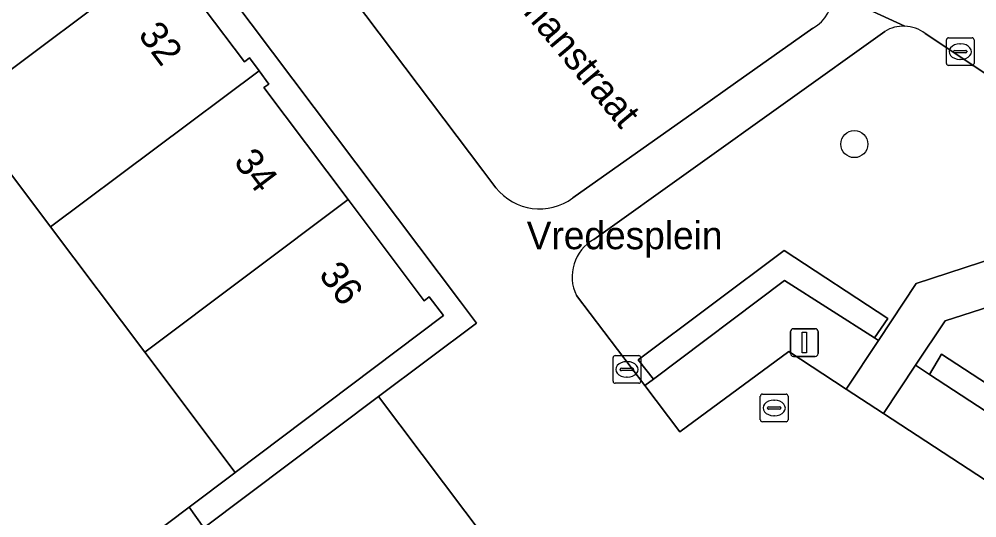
# Model space of a CAD drawing. Extents: x 160377 to 161131, y 383938 to 384853.
# Drawn here: x 160587.58 to 160622.12, y 384619.15 to 384637.16 of the extents above; entities that cross this region are included whole.
import ezdxf

# ---------------------------------------------------------------- set-up
doc = ezdxf.new("R2010")
doc.units = 0
for name, color, linetype in [('IMGEO_Boom', 7, 'Continuous'), ('IMGEO_Erf', 7, 'Continuous'), ('IMGEO_Groenvoorziening', 7, 'Continuous'), ('IMGEO_Kolk', 7, 'Continuous'), ('IMGEO_Lichtmast', 7, 'Continuous'), ('IMGEO_Muur', 7, 'Continuous'), ('IMGEO_Openbare_ruimte_label', 7, 'Continuous'), ('IMGEO_Pand', 7, 'Continuous'), ('IMGEO_Pand_nummerreeks', 7, 'Continuous'), ('IMGEO_Rioolput', 7, 'Continuous'), ('IMGEO_Voetgangersgebied_open', 7, 'Continuous')]:
    doc.layers.add(name, color=color, linetype=linetype)

msp = doc.modelspace()

# ---------------------------------------------------------------- linework, layer by layer
at = {"layer": 'IMGEO_Boom'}
msp.add_circle((160617.703, 384632.647), 0.489, dxfattribs=at)
at = {"layer": 'IMGEO_Erf'}
for points in [[(160586.32, 384648.095), (160589.204, 384644.259), (160589.374, 384644.4), (160589.733, 384643.922), (160590.092, 384643.444), (160589.923, 384643.302), (160592.795, 384639.483), (160595.702, 384635.617), (160595.883, 384635.76), (160596.236, 384635.288), (160596.588, 384634.816), (160596.403, 384634.685), (160599.444, 384630.641), (160602.186, 384626.993), (160602.369, 384627.136), (160602.879, 384626.46), (160595.375, 384620.79), (160595.355, 384620.775), (160593.711, 384619.536), (160594.236, 384618.794), (160600.544, 384623.533), (160604.071, 384626.182), (160603.494, 384626.95), (160531.839, 384722.221)], [(160587.217, 384614.645), (160593.711, 384619.536), (160595.355, 384620.775), (160595.375, 384620.79), (160592.113, 384625.131), (160588.706, 384629.665), (160585.467, 384633.975), (160582.227, 384638.285), (160578.993, 384642.588), (160575.759, 384646.891), (160572.348, 384651.43), (160571.441, 384652.625), (160568.164, 384656.977), (160564.888, 384661.328), (160561.612, 384665.679), (160558.335, 384670.03)]]:
    msp.add_lwpolyline(points, dxfattribs=at)
at = {"layer": 'IMGEO_Groenvoorziening'}
for points in [[(160602.663, 384638.174), (160599.67, 384638.706), (160599.161, 384638.527), (160604.303, 384631.697), (160604.773, 384631.072)], [(160607.553, 384630.704), (160612.128, 384633.94), (160613.421, 384634.855), (160616.208, 384636.827)], [(160618.805, 384636.718), (160608.311, 384629.208)], [(160627.62, 384631.72), (160627.236, 384631.991), (160620.256, 384636.638)], [(160607.677, 384627.181), (160610.145, 384623.927), (160610.461, 384624.157), (160609.902, 384624.855), (160615.172, 384628.807), (160618.912, 384626.351), (160618.425, 384625.654), (160618.572, 384625.558), (160619.934, 384627.618), (160626.969, 384629.907)], [(160630.684, 384629.386), (160620.978, 384626.269), (160619.914, 384624.669), (160620.413, 384624.33), (160620.848, 384625.065), (160649.969, 384606.043), (160649.496, 384605.32), (160649.64, 384605.221), (160650.89, 384607.15)]]:
    msp.add_lwpolyline(points, dxfattribs=at)
for points in [[(160618.425, 384625.654), (160615.178, 384627.727), (160610.461, 384624.157), (160610.145, 384623.927), (160611.414, 384622.253), (160615.335, 384625.155), (160617.41, 384623.8), (160618.572, 384625.558)], [(160620.413, 384624.33), (160619.914, 384624.669), (160618.749, 384622.917), (160648.502, 384603.464), (160649.64, 384605.221), (160649.496, 384605.32)], [(160605.23, 384617.306), (160600.544, 384623.533), (160594.236, 384618.794), (160593.711, 384619.536), (160587.217, 384614.645), (160584.857, 384612.643), (160582.493, 384610.638), (160578.569, 384607.304), (160579.15, 384606.609), (160578.387, 384605.942), (160570.15, 384598.933), (160571.697, 384597.097), (160573.915, 384598.966), (160577.172, 384595.101), (160592.826, 384608.058)]]:
    msp.add_lwpolyline(points, close=True, dxfattribs=at)
for centre, radius, start, end in [((160615.488, 384638.077), 1.442, 299.9347, 1.4809), ((160619.474, 384635.615), 1.29, 88.0283, 121.2134), ((160619.475, 384635.627), 1.278, 52.3045, 88.0538), ((160606.354, 384632.331), 2.021, 218.534, 306.3847), ((160609.078, 384627.855), 1.555, 119.5629, 205.7001)]:
    msp.add_arc(centre, radius, start, end, dxfattribs=at)
at = {"layer": 'IMGEO_Kolk'}
for p, q in [((160621.023, 384635.559), (160621.023, 384636.411)), ((160621.098, 384636.485), (160621.95, 384636.485)), ((160621.511, 384636.265), (160621.536, 384636.265)), ((160622.024, 384636.411), (160622.024, 384635.559)), ((160621.282, 384635.979), (160621.282, 384635.991)), ((160621.72, 384635.942), (160621.322, 384635.942)), ((160621.325, 384636.028), (160621.723, 384636.028)), ((160621.766, 384635.991), (160621.766, 384635.979)), ((160621.95, 384635.485), (160621.098, 384635.485)), ((160621.534, 384635.705), (160621.509, 384635.705)), ((160609, 384624.085), (160609, 384624.937)), ((160609.075, 384625.011), (160609.927, 384625.011)), ((160609.488, 384624.791), (160609.513, 384624.791)), ((160610.001, 384624.937), (160610.001, 384624.085)), ((160609.259, 384624.505), (160609.259, 384624.517)), ((160609.697, 384624.468), (160609.299, 384624.468)), ((160609.302, 384624.554), (160609.7, 384624.554)), ((160609.743, 384624.517), (160609.743, 384624.505)), ((160609.511, 384624.231), (160609.486, 384624.231)), ((160609.927, 384624.011), (160609.075, 384624.011))]:
    msp.add_line(p, q, dxfattribs=at)
for points in [[(160621.023, 384635.559), (160621.023, 384636.411)], [(160621.098, 384636.485), (160621.95, 384636.485)], [(160622.024, 384636.411), (160622.024, 384635.559)], [(160621.95, 384635.485), (160621.098, 384635.485)], [(160609, 384624.085), (160609, 384624.937)], [(160609.075, 384625.011), (160609.927, 384625.011)], [(160610.001, 384624.937), (160610.001, 384624.085)], [(160609.927, 384624.011), (160609.075, 384624.011)]]:
    msp.add_lwpolyline(points, dxfattribs=at)
for centre, radius, start, end in [((160621.1, 384636.409), 0.0765, 91.552, 178.448), ((160621.1, 384636.409), 0.0765, 91.552, 178.448), ((160621.948, 384636.409), 0.0765, 1.552, 88.448), ((160621.948, 384636.409), 0.0765, 1.552, 88.448), ((160621.322, 384635.988), 0.0403, 85.8775, 175.7526), ((160621.319, 384635.978), 0.0366, 178.938, 274.7102), ((160621.723, 384635.985), 0.043, 264.8664, 352.4533), ((160621.727, 384635.99), 0.0386, 1.7309, 96.639), ((160621.1, 384635.561), 0.0765, 181.552, 268.448), ((160621.1, 384635.561), 0.0765, 181.552, 268.448), ((160621.948, 384635.561), 0.0765, 271.552, 358.448), ((160621.948, 384635.561), 0.0765, 271.552, 358.448), ((160609.077, 384624.935), 0.0765, 91.552, 178.448), ((160609.077, 384624.935), 0.0765, 91.552, 178.448), ((160609.925, 384624.935), 0.0765, 1.552, 88.448), ((160609.925, 384624.935), 0.0765, 1.552, 88.448), ((160609.299, 384624.514), 0.0403, 85.8775, 175.7526), ((160609.296, 384624.504), 0.0366, 178.938, 274.7102), ((160609.7, 384624.511), 0.043, 264.8664, 352.4533), ((160609.704, 384624.516), 0.0386, 1.7309, 96.639), ((160609.077, 384624.087), 0.0765, 181.552, 268.448), ((160609.077, 384624.087), 0.0765, 181.552, 268.448), ((160609.925, 384624.087), 0.0765, 271.552, 358.448), ((160609.925, 384624.087), 0.0765, 271.552, 358.448)]:
    msp.add_arc(centre, radius, start, end, dxfattribs=at)
for centre, major_axis, ratio, start_param, end_param in [((160621.51, 384635.985), (-0.387, 0.002), 0.722429, 4.712389, 7.853982), ((160621.535, 384635.985), (-0.39, 0.002), 0.717154, 1.570796, 4.712389), ((160609.487, 384624.511), (-0.387, 0.002), 0.722429, 4.712389, 7.853982), ((160609.512, 384624.511), (-0.39, 0.002), 0.717154, 1.570796, 4.712389)]:
    msp.add_ellipse(centre, major_axis=major_axis, ratio=ratio, start_param=start_param, end_param=end_param, dxfattribs=at)
at = {"layer": 'IMGEO_Lichtmast'}
for p, q in [((160615.405, 384625.082), (160615.405, 384625.882)), ((160615.405, 384625.882), (160615.405, 384625.082)), ((160615.505, 384625.982), (160616.295, 384625.982)), ((160616.295, 384625.982), (160615.505, 384625.982)), ((160616.395, 384625.882), (160616.395, 384625.082)), ((160616.395, 384625.082), (160616.395, 384625.882)), ((160616.295, 384624.982), (160615.505, 384624.982)), ((160615.505, 384624.982), (160616.295, 384624.982))]:
    msp.add_line(p, q, dxfattribs=at)
msp.add_lwpolyline([(160615.825, 384625.857), (160615.975, 384625.857), (160615.975, 384625.107), (160615.825, 384625.107), (160615.825, 384625.857)], dxfattribs=at)
for centre, start, end in [((160615.505, 384625.882), 90, 180), ((160615.505, 384625.882), 90, 180), ((160616.295, 384625.882), 0, 90), ((160616.295, 384625.882), 360, 90), ((160615.505, 384625.082), 180, 270), ((160615.505, 384625.082), 180, 270), ((160616.295, 384625.082), 270, 0), ((160616.295, 384625.082), 270, 0)]:
    msp.add_arc(centre, 0.1, start, end, dxfattribs=at)
at = {"layer": 'IMGEO_Muur'}
for points in [[(160618.425, 384625.654), (160618.912, 384626.351), (160615.172, 384628.807), (160609.902, 384624.855), (160610.461, 384624.157), (160615.178, 384627.727)], [(160649.969, 384606.043), (160620.848, 384625.065), (160620.413, 384624.33), (160649.496, 384605.32)]]:
    msp.add_lwpolyline(points, close=True, dxfattribs=at)
at = {"layer": 'IMGEO_Pand'}
for points in [[(160592.795, 384639.483), (160589.923, 384643.302), (160590.092, 384643.444), (160589.733, 384643.922), (160582.227, 384638.285), (160585.467, 384633.975)], [(160596.236, 384635.288), (160595.883, 384635.76), (160595.702, 384635.617), (160592.795, 384639.483), (160585.467, 384633.975), (160588.706, 384629.665)], [(160599.444, 384630.641), (160596.403, 384634.685), (160596.588, 384634.816), (160596.236, 384635.288), (160588.706, 384629.665), (160592.113, 384625.131)], [(160602.879, 384626.46), (160602.369, 384627.136), (160602.186, 384626.993), (160599.444, 384630.641), (160592.113, 384625.131), (160595.375, 384620.79)]]:
    msp.add_lwpolyline(points, close=True, dxfattribs=at)
at = {"layer": 'IMGEO_Rioolput'}
for p, q in [((160614.312, 384622.694), (160614.312, 384623.546)), ((160614.387, 384623.62), (160615.239, 384623.62)), ((160614.8, 384623.4), (160614.825, 384623.4)), ((160615.313, 384623.546), (160615.313, 384622.694)), ((160614.571, 384623.114), (160614.571, 384623.126)), ((160615.009, 384623.077), (160614.611, 384623.077)), ((160614.614, 384623.163), (160615.012, 384623.163)), ((160615.055, 384623.126), (160615.055, 384623.114)), ((160614.823, 384622.84), (160614.798, 384622.84)), ((160615.239, 384622.62), (160614.387, 384622.62))]:
    msp.add_line(p, q, dxfattribs=at)
for points in [[(160614.312, 384622.694), (160614.312, 384623.546)], [(160614.387, 384623.62), (160615.239, 384623.62)], [(160615.313, 384623.546), (160615.313, 384622.694)], [(160615.239, 384622.62), (160614.387, 384622.62)]]:
    msp.add_lwpolyline(points, dxfattribs=at)
for centre, radius, start, end in [((160614.389, 384623.544), 0.0765, 91.552, 178.448), ((160614.389, 384623.544), 0.0765, 91.552, 178.448), ((160615.237, 384623.544), 0.0765, 1.552, 88.448), ((160615.237, 384623.544), 0.0765, 1.552, 88.448), ((160614.611, 384623.123), 0.0403, 85.8775, 175.7526), ((160614.608, 384623.113), 0.0366, 178.938, 274.7102), ((160615.012, 384623.12), 0.043, 264.8664, 352.4533), ((160615.016, 384623.125), 0.0386, 1.7309, 96.639), ((160614.389, 384622.696), 0.0765, 181.552, 268.448), ((160614.389, 384622.696), 0.0765, 181.552, 268.448), ((160615.237, 384622.696), 0.0765, 271.552, 358.448), ((160615.237, 384622.696), 0.0765, 271.552, 358.448)]:
    msp.add_arc(centre, radius, start, end, dxfattribs=at)
for centre, major_axis, ratio, start_param, end_param in [((160614.799, 384623.12), (-0.387, 0.002), 0.722429, 4.712389, 7.853982), ((160614.824, 384623.12), (-0.39, 0.002), 0.717154, 1.570796, 4.712389)]:
    msp.add_ellipse(centre, major_axis=major_axis, ratio=ratio, start_param=start_param, end_param=end_param, dxfattribs=at)
at = {"layer": 'IMGEO_Voetgangersgebied_open'}
for points in [[(160539.968, 384717.188), (160535.283, 384723.428), (160534.832, 384724.029), (160531.839, 384722.221), (160603.494, 384626.95), (160604.071, 384626.182), (160600.544, 384623.533), (160605.23, 384617.306), (160607.339, 384614.528), (160608.482, 384613.028), (160611.972, 384615.646), (160634.758, 384585.358), (160653.945, 384599.94), (160649.862, 384602.565), (160648.502, 384603.464), (160618.749, 384622.917), (160617.41, 384623.8), (160615.335, 384625.155)], [(160604.773, 384631.072), (160604.303, 384631.697), (160599.161, 384638.527), (160596.343, 384642.27), (160584.207, 384658.391), (160549.861, 384704.03), (160544.079, 384711.713)], [(160616.93, 384638.114), (160619.518, 384636.904)], [(160619.518, 384636.904), (160616.93, 384638.114)], [(160616.208, 384636.827), (160613.421, 384634.855), (160612.128, 384633.94), (160607.553, 384630.704)], [(160608.311, 384629.208), (160618.805, 384636.718)], [(160620.256, 384636.638), (160627.236, 384631.991), (160627.62, 384631.72)], [(160626.969, 384629.907), (160619.934, 384627.618), (160618.572, 384625.558), (160617.41, 384623.8), (160618.749, 384622.917), (160619.914, 384624.669), (160620.978, 384626.269), (160630.684, 384629.386)], [(160615.335, 384625.155), (160611.414, 384622.253), (160610.145, 384623.927), (160607.677, 384627.181)]]:
    msp.add_lwpolyline(points, dxfattribs=at)
for centre, radius, start, end in [((160615.488, 384638.077), 1.442, 299.9347, 1.4809), ((160619.474, 384635.615), 1.29, 88.0283, 121.2134), ((160619.475, 384635.627), 1.278, 52.3045, 88.0538), ((160606.354, 384632.331), 2.021, 218.534, 306.3847), ((160609.078, 384627.855), 1.555, 119.5629, 205.7001)]:
    msp.add_arc(centre, radius, start, end, dxfattribs=at)

# ---------------------------------------------------------------- texts
at = {"layer": 'IMGEO_Openbare_ruimte_label'}
msp.add_text('Karel Doormanstraat', height=1, rotation=310.0548, dxfattribs=at).set_placement((160601.355, 384642.602))
msp.add_text('Vredesplein', height=1, dxfattribs=at).set_placement((160605.886, 384628.852))
at = {"layer": 'IMGEO_Pand_nummerreeks'}
for s, rotation, p in [('32', 306.9441, (160591.844, 384636.588)), ('34', 306.9384, (160595.287, 384632.01)), ('36', 306.9384, (160598.357, 384627.926))]:
    msp.add_text(s, height=1, rotation=rotation, dxfattribs=at).set_placement(p)

doc.saveas('drawing.dxf')
